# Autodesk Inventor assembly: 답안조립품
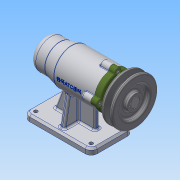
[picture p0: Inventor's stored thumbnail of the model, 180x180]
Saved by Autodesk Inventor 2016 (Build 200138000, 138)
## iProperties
Created: 2019-07
Part Number: 답안조립품
Material: 일반
Document SubType Name: Assembly
Designer: 3sil_cad0123
Author: 3sil_cad0123
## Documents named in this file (12)
- C:\Users\3sil_cad0123\Desktop\490704V1038\답안조립품.iam
- C:\Users\3sil_cad0123\Desktop\490704V1038\본체.ipt
- C:\Users\3sil_cad0123\Desktop\490704V1038\V벨트풀리.ipt
- C:\Users\3sil_cad0123\Desktop\490704V1038\멈춤나사 M3.ipt
- C:\Users\3sil_cad0123\Desktop\490704V1038\베어링 6004.ipt
- C:\Users\3sil_cad0123\Desktop\490704V1038\베어링 51202.ipt
- C:\Users\3sil_cad0123\Desktop\490704V1038\볼트 M4.ipt
- C:\Users\3sil_cad0123\Desktop\490704V1038\어댑터슬리브.ipt
- C:\Users\3sil_cad0123\Desktop\490704V1038\오일 실.ipt
- C:\Users\3sil_cad0123\Desktop\490704V1038\축.ipt
- C:\Users\3sil_cad0123\Desktop\490704V1038\커버.ipt
- C:\Users\3sil_cad0123\Desktop\490704V1038\키 5 x 5 x 16.ipt
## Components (1 placed, 1 different names)
1. V벨트풀리:1 — 각도:2
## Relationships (1: Angle 1)
- 각도:2 [Angle]: V벨트풀리:1
